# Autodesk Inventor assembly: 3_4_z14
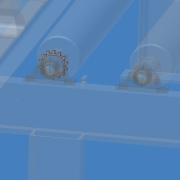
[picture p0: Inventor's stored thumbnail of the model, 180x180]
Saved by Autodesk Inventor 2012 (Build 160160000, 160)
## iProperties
Company: CAD-Verlag
Created: 2004-09
Part Number: 3_4_z14
Document SubType Name: Assembly
Designer: Greiling
Manufacturer: Standard
Standards Organization: Custom
Control State: 0
Master: False
Checked Out: False
Shininess: 64.0
Length Units: 11269
Angle Units: 11279
Time Units: 11290
Mass Units: 11283
Length Display Precision: 3
Angle Display Precision: 2
Compacted: True
Density: 0.0
Volumn: 0.0
Area: 0.0
PropertySet Name: Model Information
Author: Jürgen Kronas
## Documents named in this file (2)
- C:\DemoDaten2012\CAD Daten\Daten Vault 2012 Inventor\Kapitel 6\6.4\Rollenbahn\Rollenbahn 1400\3_4_z14.iam
- C:\DemoDaten2012\CAD Daten\Daten Vault 2012 Inventor\Kapitel 6\6.4\Rollenbahn\Rollenbahn 1400\N0233110094CWYB.ipt
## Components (1 placed, 1 different names)
1. Kettentyp 12 B:1
